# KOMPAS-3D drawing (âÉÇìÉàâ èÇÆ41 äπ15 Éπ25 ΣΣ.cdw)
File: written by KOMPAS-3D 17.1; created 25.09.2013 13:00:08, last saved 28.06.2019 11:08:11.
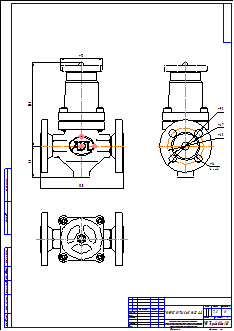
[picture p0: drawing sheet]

Sheet 1: A2, portrait

Title block, sheet 1: name: ГРАНРЕГ КАТ41 Ду15 Ру25 фф; material: Внимание! Данный продукт является объектом авторского права ООО «Торговый Дом АДЛ». / Запрещается изменение, копирование, распространение / (в том числе путем копирования на другие сайты и ресурсы в Интернете) / или любое иное использование информации и объектов без предварительного / согласия правообладателя (ООО «Торговый Дом АДЛ»).; mass: 7,3; sheets: 1; organisation: ООО "Торговый дом АДЛ"; sheet format: A2; stored path: \\adlc.lan\data\АДЛ_ПКД\3D-модели\ADL production\Клапаны КАТ ГРАНРЕГ\КАТ41\KOMPAS 2D\ГРАНРЕГ КАТ41 Ду15 Ру25 фф.cdw

Views: Вид 1, Проекционный вид 2
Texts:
  Klimkovich
  ADL
Dimensions and other numbers on the sheet: 75; 150; 57; 95; 47; 65; 14; 4 отв.; 1:1; 1; 7,3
